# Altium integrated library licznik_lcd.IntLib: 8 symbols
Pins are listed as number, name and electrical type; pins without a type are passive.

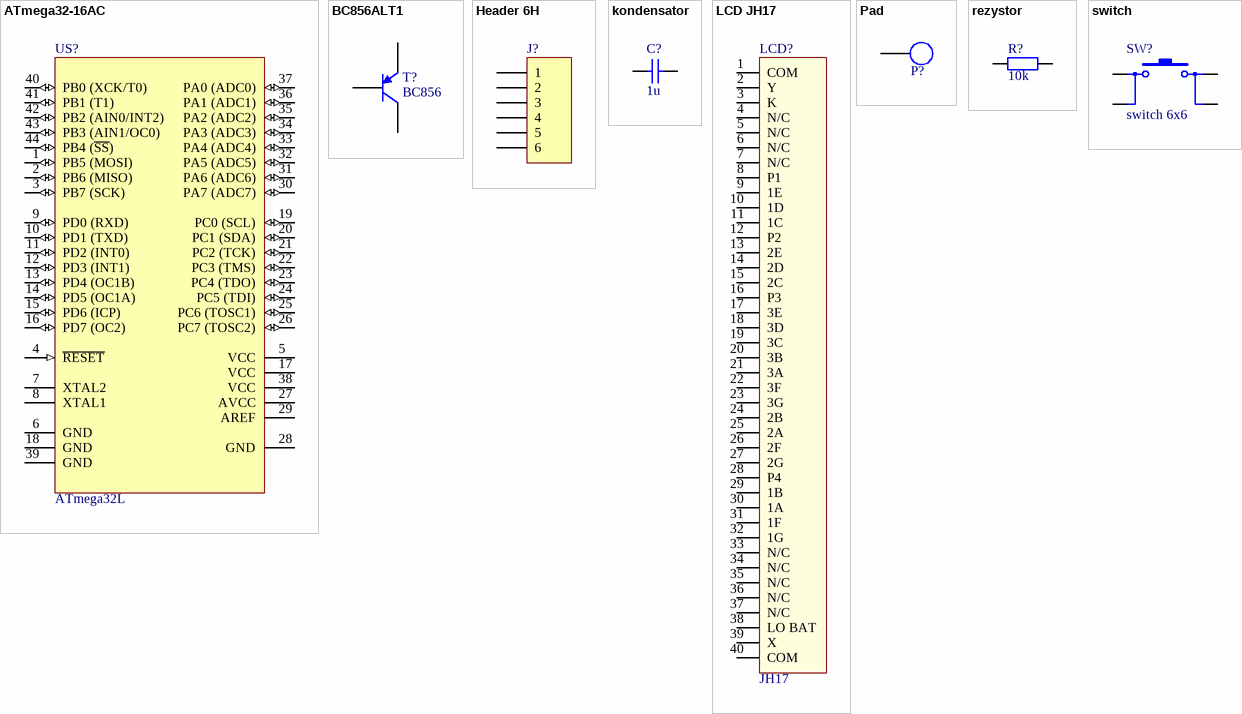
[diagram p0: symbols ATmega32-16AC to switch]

## ATmega32-16AC
designator US?, comment ATmega32L
8-Bit AVR Microcontroller with 32K Bytes of In-System Programmable Flash Memory
footprint 44A_N (Thin QFP, 44-Leads, Body 10x10mm, Pitch 0.8mm, IPC Medium Density)
footprint 44A_L (Thin QFP, 44-Leads, Body 10x10mm, Pitch 0.8mm, IPC High Density)
footprint 44A_M (Thin QFP, 44-Leads, Body 10x10mm, Pitch 0.8mm, IPC Low Density)
3D model ATMEGA32-44A (44-Pin Thin Quad Flat Pack 0.8 mm Pitch)
pins: 1 PB5 (MOSI) (io), 2 PB6 (MISO) (io), 3 PB7 (SCK) (io), 4 ~{RESET} (in), 5 VCC (power), 6 GND (power), 7 XTAL2, 8 XTAL1, 9 PD0 (RXD) (io), 10 PD1 (TXD) (io), 11 PD2 (INT0) (io), 12 PD3 (INT1) (io), 13 PD4 (OC1B) (io), 14 PD5 (OC1A) (io), 15 PD6 (ICP) (io), 16 PD7 (OC2) (io), 17 VCC (power), 18 GND (power), 19 PC0 (SCL) (io), 20 PC1 (SDA) (io), 21 PC2 (TCK) (io), 22 PC3 (TMS) (io), 23 PC4 (TDO) (io), 24 PC5 (TDI) (io), 25 PC6 (TOSC1) (io), 26 PC7 (TOSC2) (io), 27 AVCC (power), 28 GND (power), 29 AREF, 30 PA7 (ADC7) (io), 31 PA6 (ADC6) (io), 32 PA5 (ADC5) (io), 33 PA4 (ADC4) (io), 34 PA3 (ADC3) (io), 35 PA2 (ADC2) (io), 36 PA1 (ADC1) (io), 37 PA0 (ADC0) (io), 38 VCC (power), 39 GND (power), 40 PB0 (XCK/T0) (io), 41 PB1 (T1) (io), 42 PB2 (AIN0/INT2) (io), 43 PB3 (AIN1/OC0) (io), 44 PB4 (~{SS}) (io)

## BC856ALT1
designator T?, comment BC856
General Purpose Transistor PNP Silicon
footprint 318-08 (SOT-23; 3 Leads; Body 3.0 x 2.6 mm, inc. leads (LxW max))
simulation model BC856ALT1 (PNP)
signal-integrity model BC856ALT1
pins: 1 B, 2 E, 3 C

## Header 6H
designator J?
Header, 6-Pin, Right Angle
footprint HDR1X6H (Connector; Header; 6 Position; Right Angle)
signal-integrity model Connector
pins: 1, 2, 3, 4, 5, 6

## kondensator
designator C?, comment 1u
footprint kond 2,5mm
footprint kond 7,5mm
footprint kond 10mm
footprint MELF-0805 (Metal Electrode Face (MELF) Resistor; Body 2 x 1.4 mm (LxDia))
footprint MELF-1206 (Metal Electrode Face (MELF) Resistor; Body 3.2 x 1.8 mm (LxDia))
footprint kond 15mm
footprint kond 5mm chudy
footprint kond 5mm gruby
footprint kond 5mm sredni
pins: 1, 2

## LCD JH17
designator LCD?, comment JH17
footprint LCD JH17
pins: 1 COM, 2 Y, 3 K, 4 N/C, 5 N/C, 6 N/C, 7 N/C, 8 P1, 9 1E, 10 1D, 11 1C, 12 P2, 13 2E, 14 2D, 15 2C, 16 P3, 17 3E, 18 3D, 19 3C, 20 3B, 21 3A, 22 3F, 23 3G, 24 2B, 25 2A, 26 2F, 27 2G, 28 P4, 29 1B, 30 1A, 31 1F, 32 1G, 33 N/C, 34 N/C, 35 N/C, 36 N/C, 37 N/C, 38 LO BAT, 39 X, 40 COM

## Pad
designator P?, comment WE  (value not drawn)
Pad
footprint pad fi 0,8mm
footprint pad fi 1,5mm
footprint pad fi 1mm
footprint pad fi 2mm
footprint pad fi 2,5mm
footprint pad fi 4mm
footprint Pad SMD 2x4mm
pins: 1

## rezystor
designator R?, comment 10k
footprint rez 7,5mm
footprint rez 10mm
footprint rez 12,5mm
footprint rez 15mm
footprint rez 17,5mm
footprint MELF-0805 (Metal Electrode Face (MELF) Resistor; Body 2 x 1.4 mm (LxDia))
footprint MELF-1206 (Metal Electrode Face (MELF) Resistor; Body 3.2 x 1.8 mm (LxDia))
footprint rez_bocznik 20mm
pins: 1, 2

## switch
designator SW?, comment switch 6x6
footprint tact switch 12x12
footprint tact switch 6x6
pins: 1, 2, 3, 4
